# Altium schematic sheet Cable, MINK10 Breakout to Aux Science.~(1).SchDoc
size B; Organization: Monterey Bay Aquarium Research Institute; Address1: 7700 Sandholdt Rd; Address2: Moss Landing, CA 95039-9644; CompanyName: MBARI
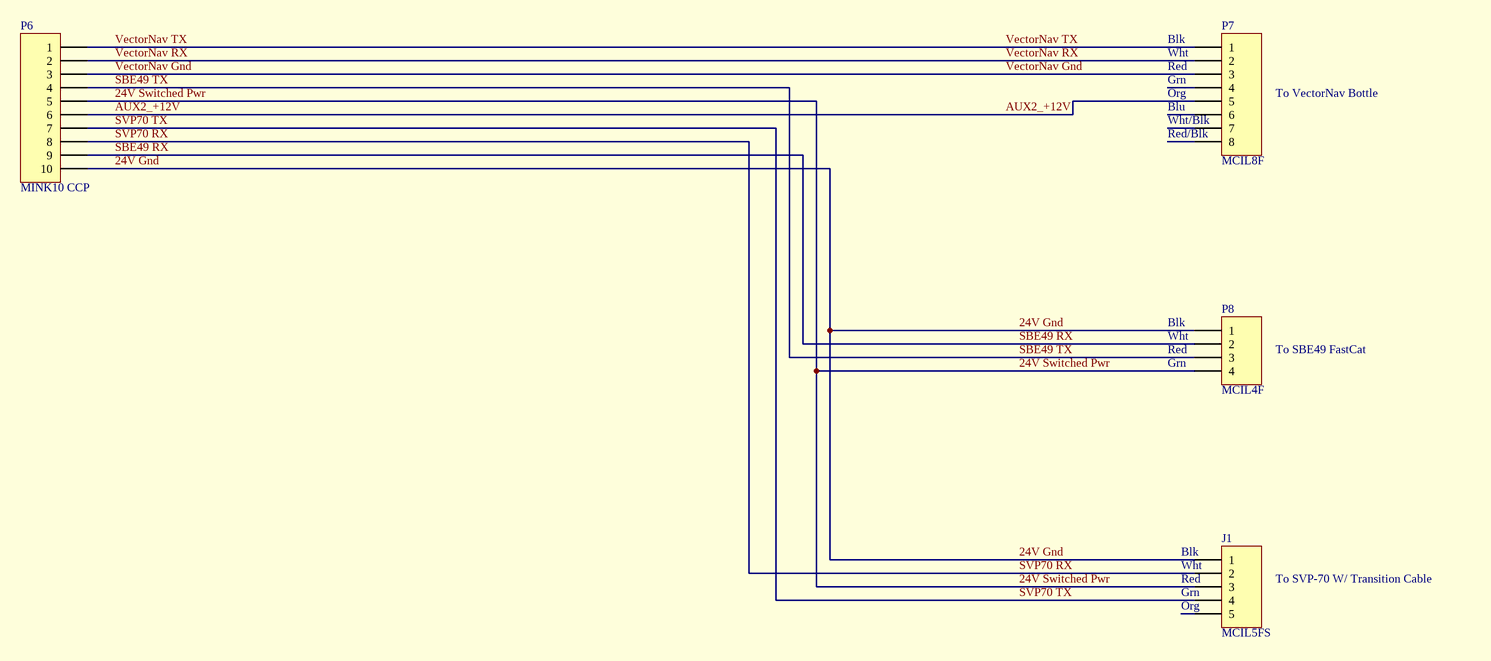
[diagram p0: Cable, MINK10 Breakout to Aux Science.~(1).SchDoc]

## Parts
J1  MCIL5FS  [HDR1X5]
P6  MINK10 CCP  [HDR1X10]
P7  MCIL8F  [HDR1X8]
P8  MCIL4F  [HDR1X4]

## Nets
24V Gnd: J1.1 P6.10 P8.1
24V Switched Pwr: J1.3 P6.5 P8.4
AUX2_+12V: P6.6 P7.5
SBE49 RX: P6.9 P8.2
SBE49 TX: P6.4 P8.3
SVP70 RX: J1.2 P6.8
SVP70 TX: J1.4 P6.7
VectorNav Gnd: P6.3 P7.3
VectorNav RX: P6.2 P7.2
VectorNav TX: P6.1 P7.1

Not connected (* = marked no-connect by the designer): J1 5; P7 4 6 7 8

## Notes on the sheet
- (near P7) Red
- (near P7) Blk
- (near P7) Wht
- (near P7) Grn
- (near P7) Org
- (near P7) Blu
- (near P7) Wht/Blk
- (near P7) Red/Blk
- To VectorNav Bottle
- (near P8) Blk
- (near P8) Wht
- (near P8) Red
- (near P8) Grn
- To SBE49 FastCat
- (near J1) Red
- (near J1) Grn
- (near J1) Blk
- (near J1) Wht
- (near J1) Org
- To SVP-70 W/ Transition Cable

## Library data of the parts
J1 = Header 5: Header, 5-Pin
P6 = Header 10: Header, 10-Pin
P7 = Header 8: Header, 8-Pin
P8 = Header 4: Header, 4-Pin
